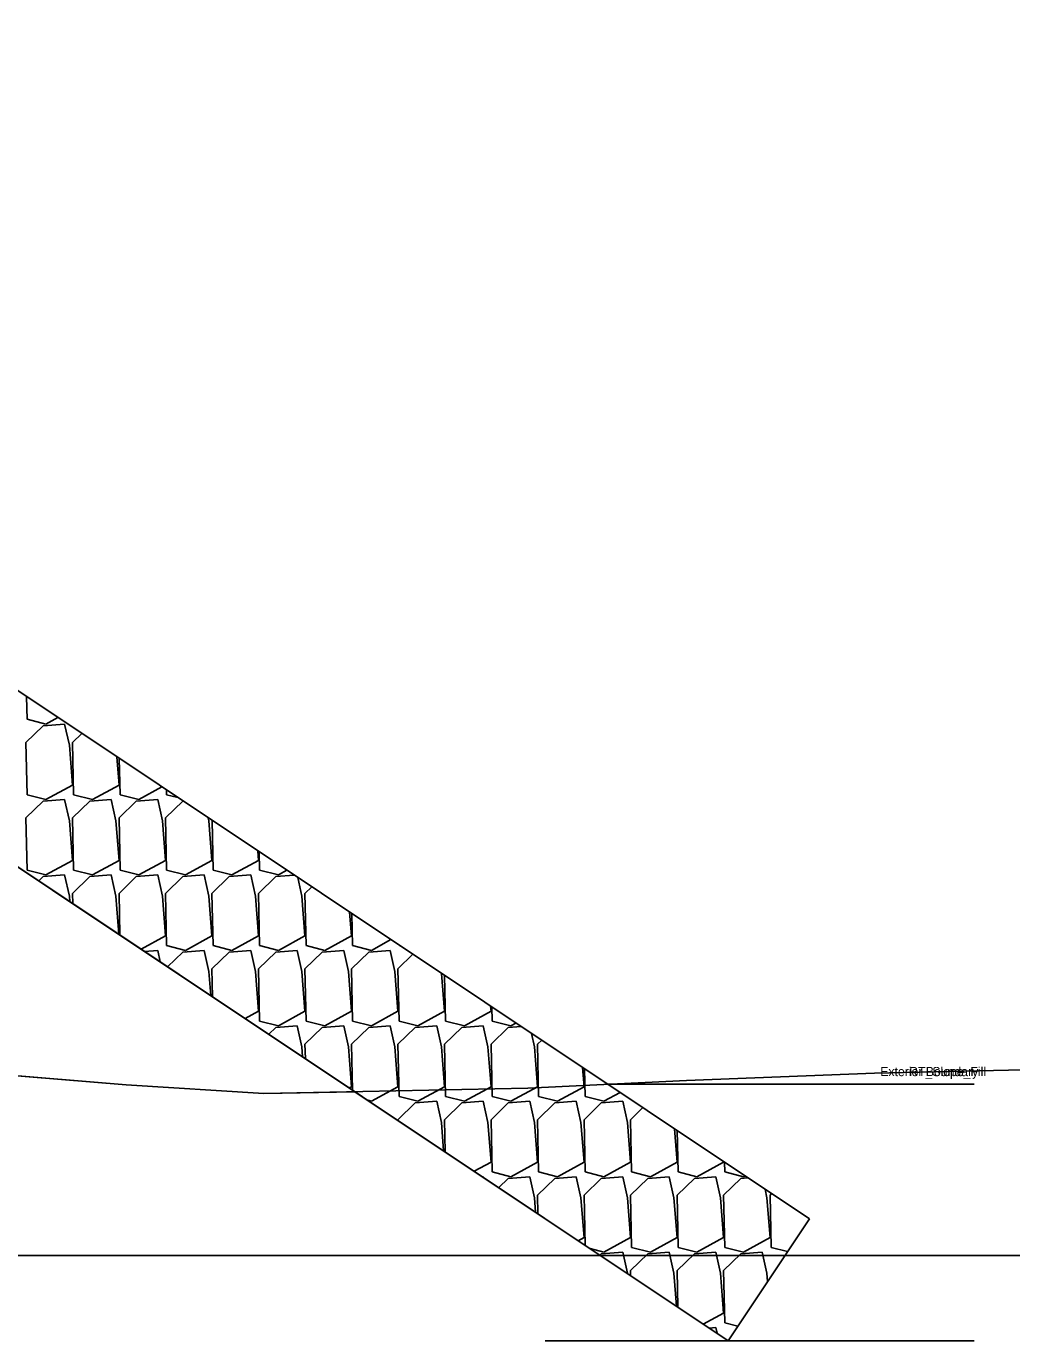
# Model space of a CAD drawing. Extents: x -26 to 2903, y -10 to 63.
# Drawn here: x 2782.74 to 2796.2, y -1.17 to 16.78 of the extents above; entities that cross this region are included whole.
import ezdxf

# ---------------------------------------------------------------- set-up
doc = ezdxf.new("R2010")
doc.units = 0
for name, color, linetype in [('Default', 7, 'Continuous'), ('Exist Cross Section Cell', 7, 'Continuous'), ('Exist XS Ground Line', 7, 'Continuous'), ('Prop CMT Slope Grass', 7, 'Continuous'), ('Prop XS Earthwork Shape', 7, 'Continuous'), ('Prop XS SE Text', 7, 'Continuous'), ('Scratch_Level_0', 7, 'Continuous'), ('Scratch_Level_3', 7, 'Continuous')]:
    doc.layers.add(name, color=color, linetype=linetype)

msp = doc.modelspace()

# ---------------------------------------------------------------- linework, layer by layer
at = {"layer": 'Default'}
for p, q in [((2765.416, 16.775), (2792.325, -1.165)), ((2792.325, -1.165), (2793.434, 0.499))]:
    msp.add_line(p, q, dxfattribs=at)
at = {"layer": 'Exist Cross Section Cell'}
msp.add_line((2750, 0), (2900, 0), dxfattribs=at)
at = {"layer": 'Exist XS Ground Line'}
for p, q in [((2778.518, 2.792), (2784.103, 2.328)), ((2794.321, 2.485), (2796.556, 2.535)), ((2789.587, 2.284), (2791.753, 2.385)), ((2791.753, 2.385), (2794.321, 2.485)), ((2784.103, 2.328), (2785.984, 2.207)), ((2785.984, 2.207), (2789.587, 2.284))]:
    msp.add_line(p, q, dxfattribs=at)
at = {"layer": 'Prop CMT Slope Grass'}
msp.add_line((2765.414, 16.776), (2787.227, 2.233), dxfattribs=at)
at = {"layer": 'Prop XS Earthwork Shape'}
msp.add_lwpolyline([(2765.97, 5.384), (2767.109, 5.022), (2768.829, 4.549), (2774.913, 3.32), (2776.338, 3.016), (2777.711, 2.83), (2778.518, 2.792), (2784.103, 2.328), (2785.984, 2.207), (2787.227, 2.233), (2766.568, 16.006)], dxfattribs=at)
at = {"layer": 'Prop XS SE Text'}
for p, q in [((2769.5, 16.457), (2793.435, 0.5)), ((2782.745, 7.625), (2782.752, 7.317)), ((2782.973, 7.229), (2782.737, 7)), ((2782.752, 7.317), (2783.008, 7.252)), ((2783.265, 7.252), (2782.973, 7.229)), ((2783.008, 7.252), (2783.172, 7.341)), ((2783.329, 6.962), (2783.265, 7.252)), ((2782.737, 7), (2782.752, 6.287)), ((2783.499, 7.123), (2783.372, 7)), ((2783.372, 7), (2783.387, 6.287)), ((2783.372, 6.42), (2783.329, 6.962)), ((2784.007, 6.42), (2783.976, 6.805)), ((2784.011, 6.781), (2784.022, 6.287)), ((2782.752, 6.287), (2783.008, 6.222)), ((2783.008, 6.222), (2783.372, 6.42)), ((2783.387, 6.287), (2783.643, 6.222)), ((2783.643, 6.222), (2784.007, 6.42)), ((2784.022, 6.287), (2784.278, 6.222)), ((2784.278, 6.222), (2784.593, 6.394)), ((2784.655, 6.352), (2784.657, 6.287)), ((2784.657, 6.287), (2784.812, 6.248)), ((2782.973, 6.199), (2782.737, 5.971)), ((2783.265, 6.222), (2782.973, 6.199)), ((2783.329, 5.933), (2783.265, 6.222)), ((2783.608, 6.199), (2783.372, 5.971)), ((2783.9, 6.222), (2783.608, 6.199)), ((2783.964, 5.933), (2783.9, 6.222)), ((2784.242, 6.199), (2784.007, 5.971)), ((2784.535, 6.222), (2784.242, 6.199)), ((2784.599, 5.933), (2784.535, 6.222)), ((2784.877, 6.199), (2784.641, 5.971)), ((2784.884, 6.2), (2784.877, 6.199)), ((2782.737, 5.971), (2782.752, 5.257)), ((2783.372, 5.391), (2783.329, 5.933)), ((2783.372, 5.971), (2783.387, 5.257)), ((2784.007, 5.391), (2783.964, 5.933)), ((2784.007, 5.971), (2784.022, 5.257)), ((2784.641, 5.391), (2784.599, 5.933)), ((2784.641, 5.971), (2784.657, 5.257)), ((2785.234, 5.933), (2785.225, 5.972)), ((2785.276, 5.391), (2785.234, 5.933)), ((2785.277, 5.937), (2785.292, 5.257)), ((2783.008, 5.193), (2783.372, 5.391)), ((2783.643, 5.193), (2784.007, 5.391)), ((2784.278, 5.193), (2784.641, 5.391)), ((2784.913, 5.193), (2785.276, 5.391)), ((2785.548, 5.193), (2785.911, 5.391)), ((2785.911, 5.391), (2785.901, 5.522)), ((2785.921, 5.508), (2785.927, 5.257)), ((2782.752, 5.257), (2783.008, 5.193)), ((2783.387, 5.257), (2783.643, 5.193)), ((2784.022, 5.257), (2784.278, 5.193)), ((2784.657, 5.257), (2784.913, 5.193)), ((2785.292, 5.257), (2785.548, 5.193)), ((2785.927, 5.257), (2786.183, 5.193)), ((2786.183, 5.193), (2786.299, 5.256)), ((2782.973, 5.17), (2782.912, 5.111)), ((2783.265, 5.193), (2782.973, 5.17)), ((2783.329, 4.903), (2783.265, 5.193)), ((2783.608, 5.17), (2783.372, 4.941)), ((2783.9, 5.193), (2783.608, 5.17)), ((2783.964, 4.903), (2783.9, 5.193)), ((2784.242, 5.17), (2784.007, 4.941)), ((2784.535, 5.193), (2784.242, 5.17)), ((2784.599, 4.903), (2784.535, 5.193)), ((2784.877, 5.17), (2784.641, 4.941)), ((2785.17, 5.193), (2784.877, 5.17)), ((2785.234, 4.903), (2785.17, 5.193)), ((2785.512, 5.17), (2785.276, 4.941)), ((2785.805, 5.193), (2785.512, 5.17)), ((2785.869, 4.903), (2785.805, 5.193)), ((2786.147, 5.17), (2785.911, 4.941)), ((2786.399, 5.19), (2786.147, 5.17)), ((2786.504, 4.903), (2786.448, 5.157)), ((2786.638, 5.03), (2786.546, 4.941)), ((2783.335, 4.829), (2783.329, 4.903)), ((2783.372, 4.941), (2783.375, 4.802)), ((2784.005, 4.382), (2783.964, 4.903)), ((2784.007, 4.941), (2784.019, 4.373)), ((2784.641, 4.361), (2784.599, 4.903)), ((2784.641, 4.941), (2784.657, 4.228)), ((2785.276, 4.361), (2785.234, 4.903)), ((2785.276, 4.941), (2785.292, 4.228)), ((2785.911, 4.361), (2785.869, 4.903)), ((2785.911, 4.941), (2785.927, 4.228)), ((2786.546, 4.361), (2786.504, 4.903)), ((2786.546, 4.941), (2786.562, 4.228)), ((2787.181, 4.361), (2787.156, 4.685)), ((2787.187, 4.664), (2787.197, 4.228)), ((2784.308, 4.18), (2784.641, 4.361)), ((2784.913, 4.163), (2785.276, 4.361)), ((2785.548, 4.163), (2785.911, 4.361)), ((2786.183, 4.163), (2786.546, 4.361)), ((2786.818, 4.163), (2787.181, 4.361)), ((2787.452, 4.163), (2787.72, 4.309)), ((2784.535, 4.163), (2784.354, 4.149)), ((2784.57, 4.005), (2784.535, 4.163)), ((2784.657, 4.228), (2784.913, 4.163)), ((2784.877, 4.14), (2784.67, 3.939)), ((2785.17, 4.163), (2784.877, 4.14)), ((2785.234, 3.873), (2785.17, 4.163)), ((2785.512, 4.14), (2785.276, 3.912)), ((2785.292, 4.228), (2785.548, 4.163)), ((2785.805, 4.163), (2785.512, 4.14)), ((2785.869, 3.873), (2785.805, 4.163)), ((2786.147, 4.14), (2785.911, 3.912)), ((2785.927, 4.228), (2786.183, 4.163)), ((2786.44, 4.163), (2786.147, 4.14)), ((2786.504, 3.873), (2786.44, 4.163)), ((2786.782, 4.14), (2786.546, 3.912)), ((2786.562, 4.228), (2786.818, 4.163)), ((2787.075, 4.163), (2786.782, 4.14)), ((2787.139, 3.873), (2787.075, 4.163)), ((2787.417, 4.14), (2787.181, 3.912)), ((2787.197, 4.228), (2787.452, 4.163)), ((2787.71, 4.163), (2787.417, 4.14)), ((2787.774, 3.873), (2787.71, 4.163)), ((2787.831, 4.235), (2787.832, 4.228)), ((2787.832, 4.228), (2787.848, 4.224)), ((2788.02, 4.109), (2787.816, 3.912)), ((2785.26, 3.545), (2785.234, 3.873)), ((2785.276, 3.912), (2785.285, 3.529)), ((2785.911, 3.331), (2785.869, 3.873)), ((2785.911, 3.912), (2785.927, 3.198)), ((2786.546, 3.331), (2786.504, 3.873)), ((2786.546, 3.912), (2786.562, 3.198)), ((2787.181, 3.331), (2787.139, 3.873)), ((2787.181, 3.912), (2787.197, 3.198)), ((2787.816, 3.331), (2787.774, 3.873)), ((2787.816, 3.912), (2787.832, 3.198)), ((2788.451, 3.331), (2788.41, 3.848)), ((2788.453, 3.82), (2788.466, 3.198)), ((2785.729, 3.232), (2785.911, 3.331)), ((2786.183, 3.134), (2786.546, 3.331)), ((2786.818, 3.134), (2787.181, 3.331)), ((2787.452, 3.134), (2787.816, 3.331)), ((2788.087, 3.134), (2788.451, 3.331)), ((2788.722, 3.134), (2789.086, 3.331)), ((2789.086, 3.331), (2789.081, 3.402)), ((2789.097, 3.391), (2789.101, 3.198)), ((2785.927, 3.198), (2786.183, 3.134)), ((2786.147, 3.111), (2786.051, 3.018)), ((2786.44, 3.134), (2786.147, 3.111)), ((2786.504, 2.844), (2786.44, 3.134)), ((2786.782, 3.111), (2786.546, 2.882)), ((2786.562, 3.198), (2786.818, 3.134)), ((2787.075, 3.134), (2786.782, 3.111)), ((2787.139, 2.844), (2787.075, 3.134)), ((2787.417, 3.111), (2787.181, 2.882)), ((2787.197, 3.198), (2787.452, 3.134)), ((2787.71, 3.134), (2787.417, 3.111)), ((2787.774, 2.844), (2787.71, 3.134)), ((2788.052, 3.111), (2787.816, 2.882)), ((2787.832, 3.198), (2788.087, 3.134)), ((2788.345, 3.134), (2788.052, 3.111)), ((2788.408, 2.844), (2788.345, 3.134)), ((2788.687, 3.111), (2788.451, 2.882)), ((2788.466, 3.198), (2788.722, 3.134)), ((2788.98, 3.134), (2788.687, 3.111)), ((2789.043, 2.844), (2788.98, 3.134)), ((2789.322, 3.111), (2789.086, 2.882)), ((2789.101, 3.198), (2789.357, 3.134)), ((2789.497, 3.124), (2789.322, 3.111)), ((2789.357, 3.134), (2789.426, 3.171)), ((2786.546, 2.882), (2786.551, 2.685)), ((2787.181, 2.882), (2787.195, 2.255)), ((2787.816, 2.882), (2787.832, 2.168)), ((2788.451, 2.882), (2788.466, 2.168)), ((2789.086, 2.882), (2789.101, 2.168)), ((2789.678, 2.844), (2789.637, 3.03)), ((2789.778, 2.937), (2789.721, 2.882)), ((2789.721, 2.882), (2789.736, 2.168)), ((2786.514, 2.709), (2786.504, 2.844)), ((2787.181, 2.302), (2787.139, 2.844)), ((2787.816, 2.302), (2787.774, 2.844)), ((2788.451, 2.302), (2788.408, 2.844)), ((2789.086, 2.302), (2789.043, 2.844)), ((2789.721, 2.302), (2789.678, 2.844)), ((2790.356, 2.302), (2790.335, 2.565)), ((2790.363, 2.547), (2790.371, 2.168)), ((2787.15, 2.285), (2787.181, 2.302)), ((2787.227, 2.233), (2792.325, -1.165)), ((2787.452, 2.104), (2787.816, 2.302)), ((2787.832, 2.168), (2788.087, 2.104)), ((2788.087, 2.104), (2788.451, 2.302)), ((2788.466, 2.168), (2788.722, 2.104)), ((2788.722, 2.104), (2789.086, 2.302)), ((2789.101, 2.168), (2789.357, 2.104)), ((2789.357, 2.104), (2789.721, 2.302)), ((2789.736, 2.168), (2789.992, 2.104)), ((2789.992, 2.104), (2790.356, 2.302)), ((2790.371, 2.168), (2790.627, 2.104)), ((2790.627, 2.104), (2790.847, 2.224)), ((2787.403, 2.116), (2787.452, 2.104)), ((2788.052, 2.081), (2787.816, 1.852)), ((2788.345, 2.104), (2788.052, 2.081)), ((2788.408, 1.814), (2788.345, 2.104)), ((2788.687, 2.081), (2788.451, 1.852)), ((2788.98, 2.104), (2788.687, 2.081)), ((2789.043, 1.814), (2788.98, 2.104)), ((2789.322, 2.081), (2789.086, 1.852)), ((2789.615, 2.104), (2789.322, 2.081)), ((2789.678, 1.814), (2789.615, 2.104)), ((2789.957, 2.081), (2789.721, 1.852)), ((2790.25, 2.104), (2789.957, 2.081)), ((2790.313, 1.814), (2790.25, 2.104)), ((2790.592, 2.081), (2790.356, 1.852)), ((2790.885, 2.104), (2790.592, 2.081)), ((2790.948, 1.814), (2790.885, 2.104)), ((2791.159, 2.016), (2790.991, 1.852)), ((2787.816, 1.852), (2787.816, 1.841)), ((2788.439, 1.426), (2788.408, 1.814)), ((2788.451, 1.852), (2788.461, 1.411)), ((2789.086, 1.272), (2789.043, 1.814)), ((2789.086, 1.852), (2789.101, 1.139)), ((2789.721, 1.272), (2789.678, 1.814)), ((2789.721, 1.852), (2789.736, 1.139)), ((2790.356, 1.272), (2790.313, 1.814)), ((2790.356, 1.852), (2790.371, 1.139)), ((2790.991, 1.272), (2790.948, 1.814)), ((2790.991, 1.852), (2791.006, 1.139)), ((2791.626, 1.272), (2791.59, 1.729)), ((2791.629, 1.703), (2791.641, 1.139)), ((2788.857, 1.147), (2789.086, 1.272)), ((2789.357, 1.074), (2789.721, 1.272)), ((2789.992, 1.074), (2790.356, 1.272)), ((2790.627, 1.074), (2790.991, 1.272)), ((2791.262, 1.074), (2791.626, 1.272)), ((2791.897, 1.074), (2792.261, 1.272)), ((2792.261, 1.272), (2792.26, 1.282)), ((2792.273, 1.273), (2792.276, 1.139)), ((2789.101, 1.139), (2789.357, 1.074)), ((2789.736, 1.139), (2789.992, 1.074)), ((2790.371, 1.139), (2790.627, 1.074)), ((2791.006, 1.139), (2791.262, 1.074)), ((2791.641, 1.139), (2791.897, 1.074)), ((2792.276, 1.139), (2792.532, 1.074)), ((2792.532, 1.074), (2792.554, 1.086)), ((2788.98, 1.074), (2788.967, 1.073)), ((2788.982, 1.063), (2788.98, 1.074)), ((2789.322, 1.051), (2789.191, 0.924)), ((2789.615, 1.074), (2789.322, 1.051)), ((2789.678, 0.785), (2789.615, 1.074)), ((2789.957, 1.051), (2789.721, 0.823)), ((2790.25, 1.074), (2789.957, 1.051)), ((2790.313, 0.785), (2790.25, 1.074)), ((2790.592, 1.051), (2790.356, 0.823)), ((2790.885, 1.074), (2790.592, 1.051)), ((2790.948, 0.785), (2790.885, 1.074)), ((2791.227, 1.051), (2790.991, 0.823)), ((2791.52, 1.074), (2791.227, 1.051)), ((2791.583, 0.785), (2791.52, 1.074)), ((2791.862, 1.051), (2791.626, 0.823)), ((2792.155, 1.074), (2791.862, 1.051)), ((2792.218, 0.785), (2792.155, 1.074)), ((2792.497, 1.051), (2792.261, 0.823)), ((2792.594, 1.059), (2792.497, 1.051)), ((2792.853, 0.785), (2792.827, 0.904)), ((2789.694, 0.589), (2789.678, 0.785)), ((2789.721, 0.823), (2789.726, 0.567)), ((2790.356, 0.243), (2790.313, 0.785)), ((2790.356, 0.823), (2790.371, 0.138)), ((2790.991, 0.243), (2790.948, 0.785)), ((2790.991, 0.823), (2791.006, 0.109)), ((2791.626, 0.243), (2791.583, 0.785)), ((2791.626, 0.823), (2791.641, 0.109)), ((2792.261, 0.243), (2792.218, 0.785)), ((2792.261, 0.823), (2792.276, 0.109)), ((2792.896, 0.243), (2792.853, 0.785)), ((2792.917, 0.844), (2792.896, 0.823)), ((2792.896, 0.823), (2792.911, 0.109)), ((2793.435, 0.5), (2792.325, -1.165)), ((2790.277, 0.2), (2790.356, 0.243)), ((2790.627, 0.045), (2790.991, 0.243)), ((2791.262, 0.045), (2791.626, 0.243)), ((2791.897, 0.045), (2792.261, 0.243)), ((2792.532, 0.045), (2792.896, 0.243)), ((2790.439, 0.092), (2790.627, 0.045)), ((2790.592, 0.022), (2790.573, 0.003)), ((2790.885, 0.045), (2790.592, 0.022)), ((2790.948, -0.245), (2790.885, 0.045)), ((2791.227, 0.022), (2790.991, -0.207)), ((2791.006, 0.109), (2791.262, 0.045)), ((2791.52, 0.045), (2791.227, 0.022)), ((2791.583, -0.245), (2791.52, 0.045)), ((2791.862, 0.022), (2791.626, -0.207)), ((2791.641, 0.109), (2791.897, 0.045)), ((2792.155, 0.045), (2791.862, 0.022)), ((2792.218, -0.245), (2792.155, 0.045)), ((2792.497, 0.022), (2792.261, -0.207)), ((2792.276, 0.109), (2792.532, 0.045)), ((2792.79, 0.045), (2792.497, 0.022)), ((2792.853, -0.245), (2792.79, 0.045)), ((2792.911, 0.109), (2793.136, 0.052)), ((2790.948, -0.247), (2790.948, -0.245)), ((2790.991, -0.207), (2790.992, -0.277)), ((2791.618, -0.694), (2791.583, -0.245)), ((2791.626, -0.207), (2791.637, -0.706)), ((2792.261, -0.787), (2792.218, -0.245)), ((2792.261, -0.207), (2792.276, -0.92)), ((2792.862, -0.359), (2792.853, -0.245)), ((2791.984, -0.938), (2792.261, -0.787)), ((2792.155, -0.985), (2792.065, -0.992)), ((2792.172, -1.063), (2792.155, -0.985)), ((2792.276, -0.92), (2792.457, -0.966))]:
    msp.add_line(p, q, dxfattribs=at)
at = {"layer": 'Scratch_Level_3'}
for p, q in [((2790.682, 2.335), (2795.682, 2.335)), ((2789.825, -1.165), (2795.682, -1.165))]:
    msp.add_line(p, q, dxfattribs=at)

# ---------------------------------------------------------------- texts
at = {"layer": 'Scratch_Level_0'}
for s, p in [('Exterior Boundary', (2794.4, 2.446)), ('RT_Slope_Fill', (2794.795, 2.446)), ('RT_Slope_Fill', (2794.795, 2.446))]:
    msp.add_text(s, height=0.125, dxfattribs=at).set_placement(p)

doc.saveas('drawing.dxf')
